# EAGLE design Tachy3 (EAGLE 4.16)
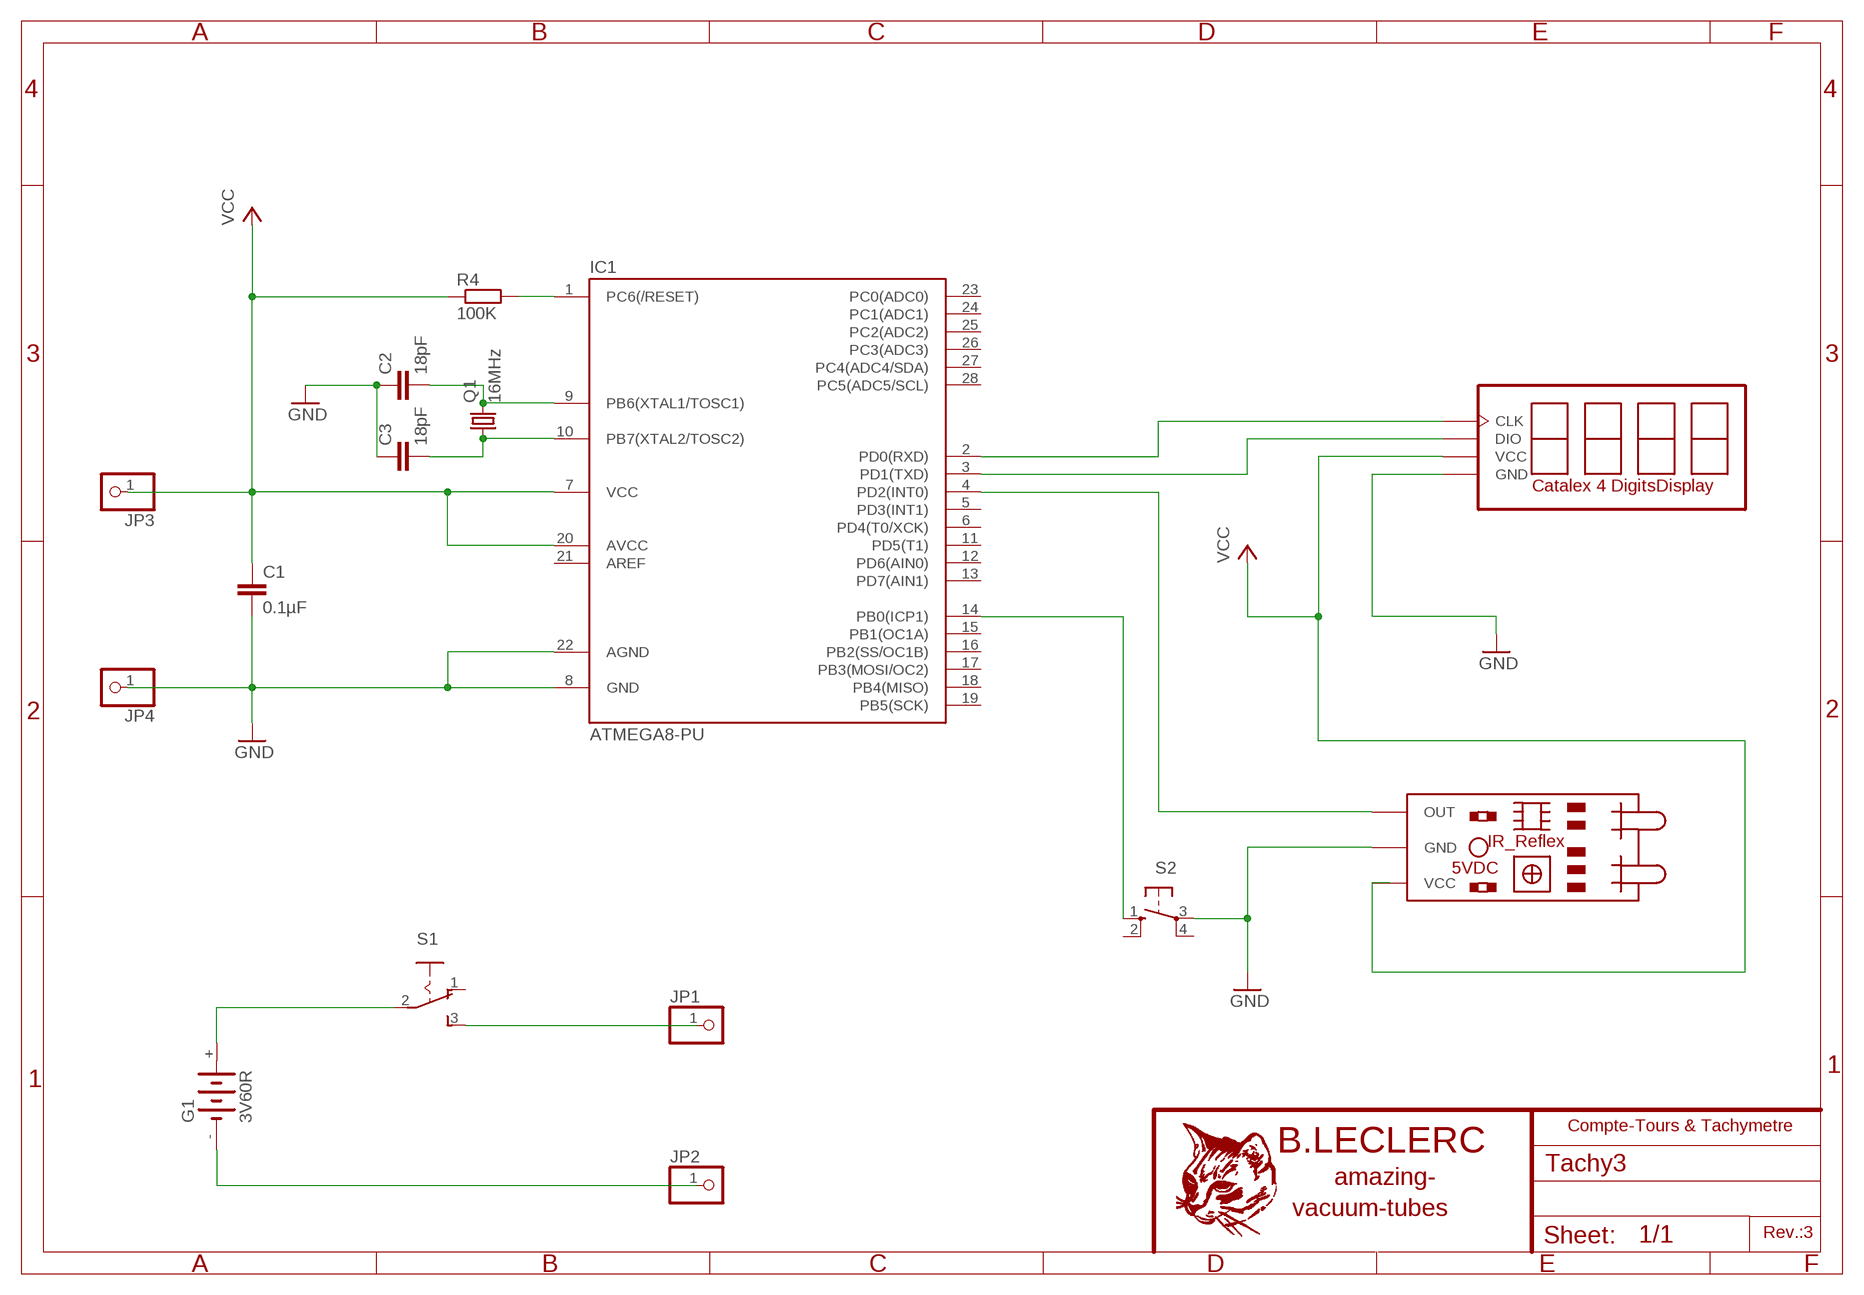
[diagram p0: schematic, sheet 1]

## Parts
C1  0.1µF  C-EUC1206K  [C1206K]
C2  18pF  C-EUC1206  [C1206]
C3  18pF  C-EUC1206  [C1206]
G1  3V60R  [3V60R]
IC1  ATMEGA8-PU  [DIL28-3]
JP1  PINHD-1X1  [1X01]
JP2  PINHD-1X1  [1X01]
JP3  PINHD-1X1  [1X01]
JP4  PINHD-1X1  [1X01]
Q1  16MHz  CRYTALHC49S  [HC49/S]
R4  100K  R-EU_M1206  [M1206]
S1  255SB  [255SB]
S2  10-XX  [B3F-10XX]
U$2  IR_REFLEX  [IR_REFLEX]
U$3  4DIGITS_DISPLAY_I2C  [4_DIGITS_DISPLAY_I2C]

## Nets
GND: C1.2 C2.1 C3.1 IC1.8(GND) IC1.22(AGND) JP4.1 S2.3(P) U$2.GND U$3.4(GND)
N$1: G1.- JP2.1
N$2: G1.+ S1.2(P)
N$3: JP1.1 S1.3(S)
N$4: IC1.1(PC6(/RESET)) R4.2
N$5: C2.2 IC1.9(PB6(XTAL1/TOSC1)) Q1.2
N$6: IC1.3(PD1(TXD)) U$3.2(DIO)
N$7: IC1.2(PD0(RXD)) U$3.1(CLK)
N$8: C3.2 IC1.10(PB7(XTAL2/TOSC2)) Q1.1
N$11: IC1.4(PD2(INT0)) U$2.OUT
N$12: IC1.14(PB0(ICP1)) S2.1(S)
VCC: C1.1 IC1.7(VCC) IC1.20(AVCC) JP3.1 R4.1
Unconnected: G1.+@1(+) IC1.5(PD3(INT1)) IC1.6(PD4(T0/XCK)) IC1.11(PD5(T1)) IC1.12(PD6(AIN0)) IC1.13(PD7(AIN1)) IC1.15(PB1(OC1A)) IC1.16(PB2(SS/OC1B)) IC1.17(PB3(MOSI/OC2)) IC1.18(PB4(MISO)) IC1.19(PB5(SCK)) IC1.21(AREF) IC1.23(PC0(ADC0)) IC1.24(PC1(ADC1)) IC1.25(PC2(ADC2)) IC1.26(PC3(ADC3)) IC1.27(PC4(ADC4/SDA)) IC1.28(PC5(ADC5/SCL)) S1.1(O) S2.2(S1) S2.4(P1)

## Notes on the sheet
- Compte-Tours & Tachymetre
- Rev.:3

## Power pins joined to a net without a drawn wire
VCC: U$2.VCC U$3.3(VCC)

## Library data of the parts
C1-C3 = rcl:C-EU: CAPACITOR, European symbol
G1 = battery:3V60R: NC ACCU Varta
IC1 = atmega8:ATMEGA8-PU
JP1-JP4 = pinhead:PINHD-1X1: PIN HEADER
Q1 = crystal:CRYTAL: CRYSTAL
R4 = rcl:R-EU_: RESISTOR, European symbol
S1 = switch:255SB: SLIDING SWITCH distributor Buerklin, 11G810
S2 = switch-omron:10-XX: OMRON SWITCH
U$2 = Arduino:IR_REFLEX
U$3 = Arduino:4DIGITS_DISPLAY_I2C

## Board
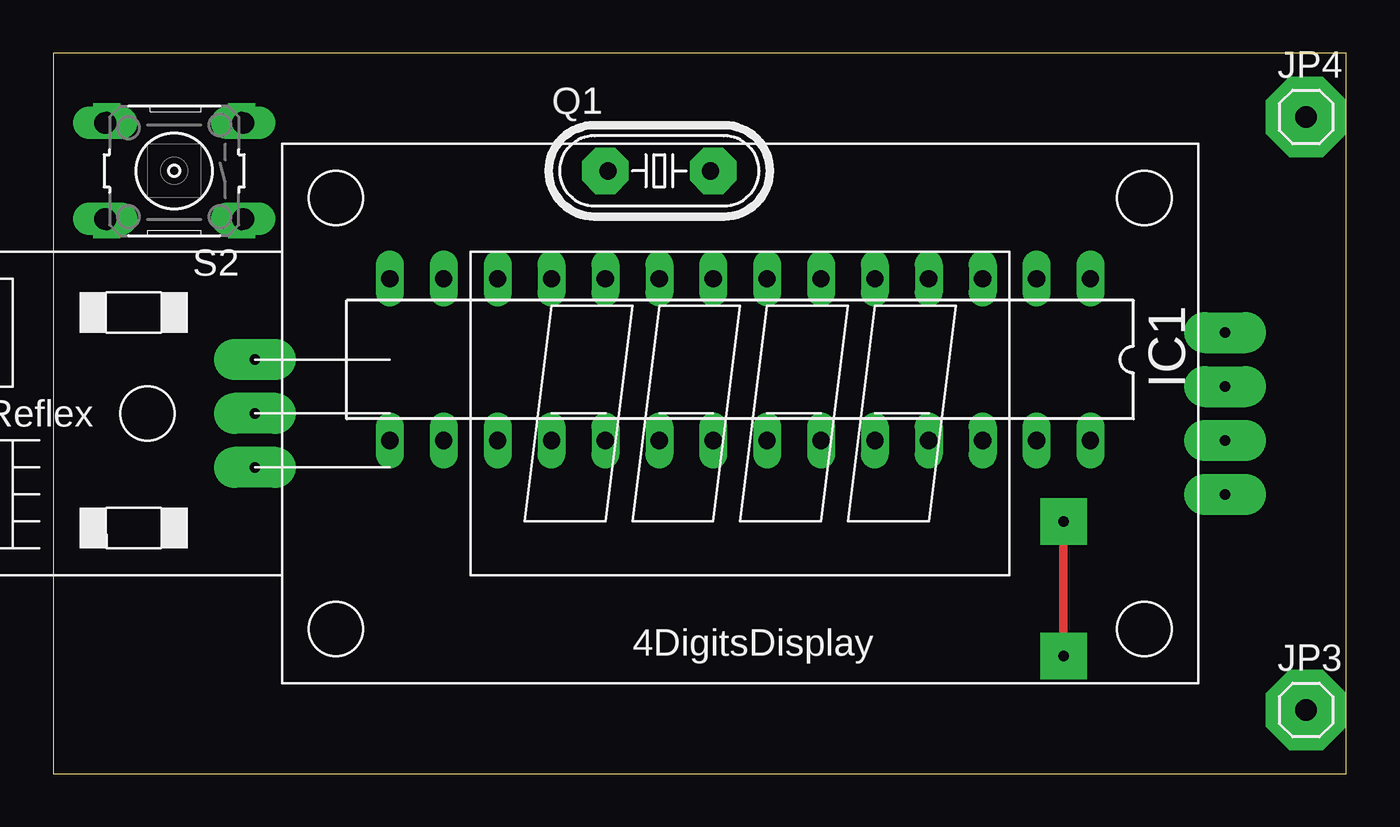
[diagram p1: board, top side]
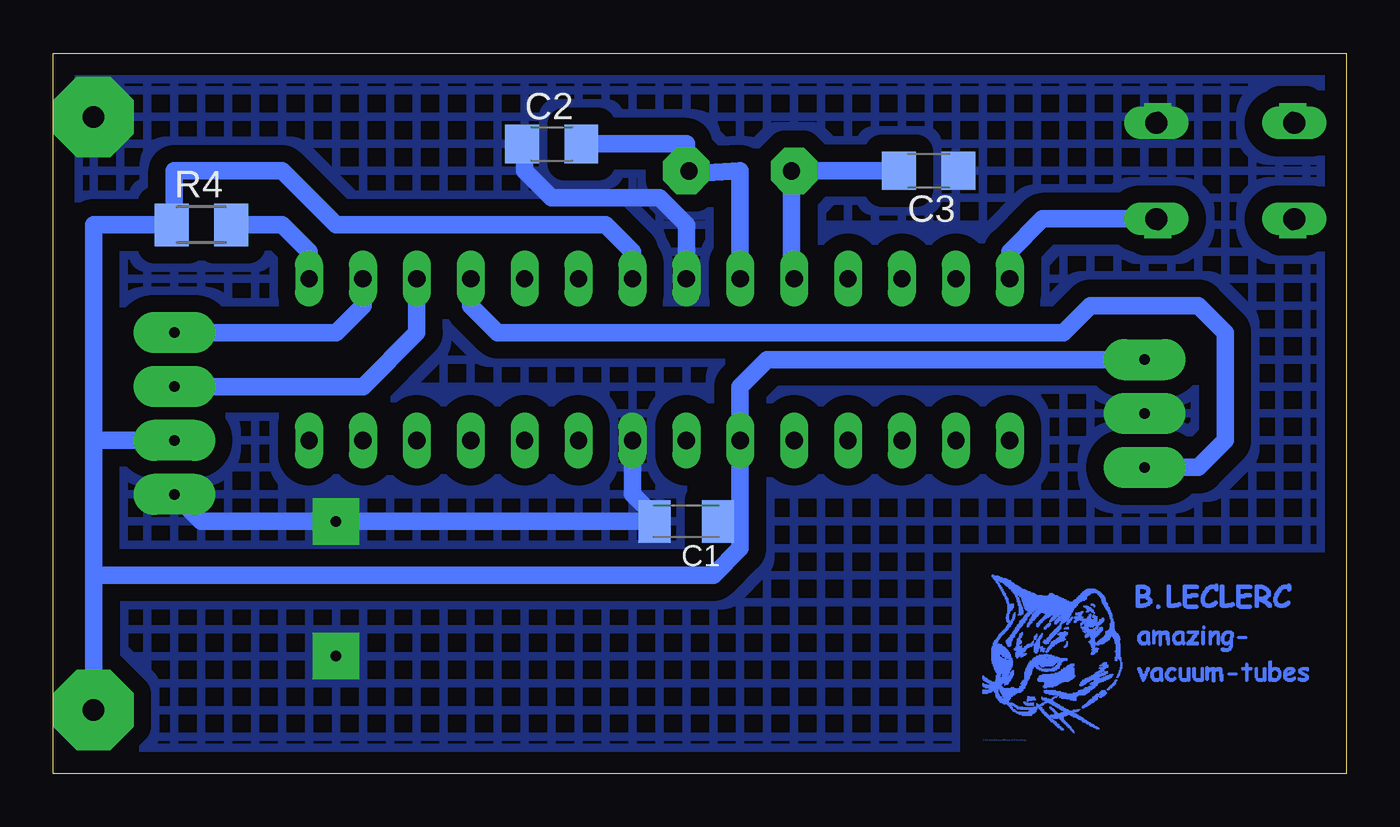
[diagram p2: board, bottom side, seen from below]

Size 60.94 x 33.96 mm. Coordinates in mm from the lower left corner, seen from the top.
Outline: 0,0 60.94,0 60.94,33.96 0,33.96 0,0
Copper layers (1*16): Top 0.035mm / dielectric 1.5mm / Bottom 0.035mm
Design rules "default": minimum track width 10mil, minimum drill 24mil, track to track 8mil, track to pad 8mil, pad to pad 8mil, via to via 8mil, smd to smd 8mil, copper to edge 40mil, drill to drill 8mil, minimum pad ring 10mil, minimum via ring 8mil, stop-mask expansion 4mil, vias tented up to drill 0mil, thermal gap 10mil

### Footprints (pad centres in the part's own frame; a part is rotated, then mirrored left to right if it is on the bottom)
C1206K = smd 1.5 x 2: 1 -1.5,0; 2 1.5,0
C1206 = smd 1.6 x 1.8: 1 -1.4,0; 2 1.4,0
3V60R = drill 1.321 pad 3.15 octagon: + -10.16,-5.08; +@1 -10.16,5.08; - 9.271,0
DIL28-3 = drill 0.813 long: 1 -16.51,-3.81; 2 -13.97,-3.81; 3 -11.43,-3.81; 4 -8.89,-3.81; 5 -6.35,-3.81; 6 -3.81,-3.81; 7 -1.27,-3.81; 8 1.27,-3.81; 9 3.81,-3.81; 10 6.35,-3.81; 11 8.89,-3.81; 12 11.43,-3.81; 13 13.97,-3.81; 14 16.51,-3.81; 15 16.51,3.81; 16 13.97,3.81; 17 11.43,3.81; 18 8.89,3.81; 19 6.35,3.81; 20 3.81,3.81; 21 1.27,3.81; 22 -1.27,3.81; 23 -3.81,3.81; 24 -6.35,3.81; 25 -8.89,3.81; 26 -11.43,3.81; 27 -13.97,3.81; 28 -16.51,3.81
1X01 = drill 1.016 octagon: 1 0,0
HC49/S = drill 0.813 round: 1 -2.413,0; 2 2.413,0
M1206 = smd 1.6 x 2: 1 -1.4,0; 2 1.4,0
255SB = drill 1.118 long: 1 -3.81,0; 2 0,0; 3 3.81,0
B3F-10XX = drill 1.016 long: 1 -3.251,2.261; 2 3.251,2.261; 3 -3.251,-2.261; 4 3.251,-2.261
IR_REFLEX = drill 0.5 pad 1.93 long: GND 0,0; OUT 0,2.54; VCC 0,-2.54
4_DIGITS_DISPLAY_I2C = drill 0.5 pad 1.93 long: 1 1.27,3.81; 2 1.27,1.27; 3 1.27,-1.27; 4 1.27,-3.81

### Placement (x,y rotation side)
C1  31.11,11.9 180 bottom
C2  37.46,29.68 0 bottom
C3  19.68,28.41 180 bottom
G1  not placed on the board
IC1  32.38,19.52 180 top
JP1  not placed on the board
JP2  not placed on the board
JP3  59.05,3.01 0 top
JP4  59.05,30.95 0 top
Q1  28.57,28.41 0 top
R4  53.97,25.87 0 bottom
S1  not placed on the board
S2  5.71,28.41 180 top
U$2  9.52,16.98 180 top
U$3  53.97,16.98 0 top
U$4  [CHAT]  17.14,1.74 0 bottom

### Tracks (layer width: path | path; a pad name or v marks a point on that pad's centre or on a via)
GND  (via drill 0.5 pad 1.27, 0.5 pad 2.18, 0.5 pad 3.81)
  Top 0.406: v47.62,11.9 v47.62,5.55
  Bottom 0.813: C3.1 18.41,28.41 | IC1.22 33.65,13.17 32.38,11.9 | C1.2 32.38,11.9 | 32.38,11.9 v47.62,11.9 53.97,11.9 U$3.4 | IC1.8 31.11,25.87 32.38,27.14 37.46,27.14 38.73,28.41 38.73,29.68 C2.1
  other vias: 8.89,30.95 31.11,23.33 59.05,30.95
  pour Bottom (isolate 0.813, no thermals, hatched): 0.63,33.49 60.32,33.49 60.32,0.47 18.41,0.47 18.41,10.63 0.63,10.63
N$1  (1 unrouted)
N$2  (1 unrouted)
N$3  (1 unrouted)
N$4
  Bottom 0.813: R4.2 50.16,25.87 48.89,24.6 IC1.1
N$5
  Bottom 0.813: IC1.9 28.57,28.41 30.98,28.28 Q1.2 31.11,28.41 31.11,29.68 C2.2
N$6
  Bottom 0.813: IC1.3 43.81,20.79 46.35,18.25 U$3.2
N$7
  Bottom 0.813: IC1.2 46.35,22.06 47.62,20.79 U$3.1
N$8
  Bottom 0.813: C3.2 Q1.1 26.16,23.46 IC1.10
N$9  (via drill 0.5 pad 3.81)
  other vias: 59.05,3.01
N$10  (via drill 0.5 pad 2.18)
  other vias: 26.03,28.41
N$11
  Bottom 0.813: IC1.4 41.27,22.06 40,20.79 13.33,20.79 12.06,22.06 6.98,22.06 5.71,20.79 5.71,15.71 6.98,14.44 U$2.OUT
N$12
  Bottom 0.813: S2.1 14.32,26.15 15.87,24.6 IC1.14
N$13  (via drill 0.5 pad 2.18)
  other vias: 31.11,28.41
N$14  (via drill 0.5 pad 1.27)
  other vias: 2.54,30.95
N$15  (via drill 0.5 pad 1.27)
  other vias: 8.89,25.87
N$17  (via drill 0.5 pad 1.27)
  other vias: 2.54,25.87
N$18  (via drill 0.5 pad 1.27)
  other vias: 20.95,15.71
N$19  (via drill 0.5 pad 1.27)
  other vias: 26.03,15.71
N$20  (via drill 0.5 pad 1.27)
  other vias: 28.57,15.71
N$21  (via drill 0.5 pad 1.27)
  other vias: 31.11,15.71
N$22  (via drill 0.5 pad 1.27)
  other vias: 43.81,15.71
N$23  (via drill 0.5 pad 1.27)
  other vias: 46.35,15.71
N$24  (via drill 0.5 pad 1.27)
  other vias: 18.41,23.33
N$25  (via drill 0.5 pad 1.27)
  other vias: 15.87,23.33
N$26  (via drill 0.5 pad 1.27)
  other vias: 23.49,23.33
N$27  (via drill 0.5 pad 1.27)
  other vias: 33.65,23.33
N$28  (via drill 0.5 pad 1.27)
  other vias: 36.19,23.33
N$29  (via drill 0.5 pad 1.27)
  other vias: 43.81,23.33
N$30  (via drill 0.5 pad 1.27)
  other vias: 46.35,23.33
N$31  (via drill 0.5 pad 1.27)
  other vias: 41.27,23.33
N$32  (via drill 0.5 pad 1.27)
  other vias: 38.73,23.33
N$34  (via drill 0.5 pad 1.27)
  other vias: 28.57,23.33
N$35  (via drill 0.5 pad 1.27)
  other vias: 26.03,23.33
N$36  (via drill 0.5 pad 1.27)
  other vias: 20.95,23.33
N$37  (via drill 0.5 pad 1.27)
  other vias: 15.87,15.71
N$38  (via drill 0.5 pad 1.27)
  other vias: 38.73,15.71
N$39  (via drill 0.5 pad 1.27)
  other vias: 36.19,15.71
N$40  (via drill 0.5 pad 1.27)
  other vias: 23.49,15.71
N$41  (via drill 0.5 pad 1.27)
  other vias: 18.41,15.71
N$42  (via drill 0.5 pad 1.27)
  other vias: 48.89,23.33
N$43  (via drill 0.5 pad 1.27)
  other vias: 48.89,15.71
N$44  (via drill 0.5 pad 1.27)
  other vias: 41.27,15.71
VCC
  Bottom 0.813: 29.84,11.9 C1.1 28.57,11.9 | 28.57,11.9 IC1.20 28.57,18.25 | 59.05,9.36 JP3.1 | 59.05,9.36 59.05,15.71 | 59.05,15.71 59.05,25.87 R4.1 55.24,25.87 55.24,28.41 50.16,28.41 47.62,25.87 34.92,25.87 33.65,24.6 IC1.7 | U$2.VCC 27.3,19.52 28.57,18.25 | 28.57,18.25 28.57,11.9 | 28.57,11.9 28.57,10.63 29.84,9.36 59.05,9.36 | 59.05,15.71 U$3.3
